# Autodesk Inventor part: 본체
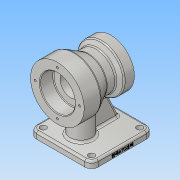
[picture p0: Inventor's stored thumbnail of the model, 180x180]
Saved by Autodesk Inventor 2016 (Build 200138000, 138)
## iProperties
Created: 2019-01
Part Number: 본체
Material: 알루미늄 6061
Document SubType Name: Modeling
Designer: Administrator
Density: 2.7 g/cm^3
Appearance: 알루미늄 - 평지
Mass: 898.816 g
Surface Area: 600.964 cm^2
Volume: 332.895 cm^3
Author: Administrator
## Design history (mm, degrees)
sketch "스케치1"
  geometry: L1 (46, -46)-(-46, -46); L2 (-46, -46)-(-46, 46); L3 (-46, 46)-(46, 46); L4 (46, 46)-(46, -46); L5 (46, -46)-(-46, 46); L6 (-46, -46)-(46, 46); 1 further point
  constraints: 12 end point, 2 midpoint, 2 parallel, 1 horizontal, 1 perpendicular
  dimensions: "d0" = 92 distance of L2.end L3.end; "d1" = 92 distance of L1.end L2.end
extrude "돌출1" new body sketch "스케치1" distance "d2" = 10; taper "d3" = 0 deg
sketch "스케치2"
  geometry: L1 (-51, 80)-(29, 80); L2 (-46, 0)-(-46, 10) reference; L3 (-51, 0)-(-51, 10); L4 (-51, 10)-(-51, 80); L5 (46, 0)-(-46, 0) reference; L6 (-51, 80)-(-51, 120); L7 (-51, 120)-(-26, 120); L8 (-26, 120)-(-5.215, 108); L9 (-5.215, 108)-(8.126, 108); L10 (8.126, 108)-(14, 115); L11 (14, 115)-(29, 115); L12 (29, 115)-(29, 80); 1 further point
  constraints: 20 end point, 3 parallel, 2 perpendicular, 2 vertical, 1 horizontal
  dimensions: "d4" = 80 distance of L1.start L1.end; "d18" = 5 distance between parallel lines of L2 L3; "d19" = 80 distance between parallel lines of L5 L1; "d21" = 30 deg angle of L9 L8; "d22" = 50 deg angle of L9 L10; "d23" = 80 diameter of L7 L1; "d24" = 70 diameter of L11 L1; "d25" = 25 distance of L6.end L7.end; "d26" = 15 distance of L10.end L11.end; "d76" = 80 horizontal distance of L11.end L6.end (derived); "d77" = 56 diameter of L9 L1
revolve "회전1" sketch "스케치2" stored, may be unused: angle "d20" = 90 deg
sketch "스케치3"
  geometry: L1 (-51, 80)-(29, 80); L2 (-51, 80)-(-51, 106); L3 (-51, 106)-(-31, 106); L4 (-31, 106)-(-31, 96); L5 (-31, 96)-(12, 96); L6 (12, 96)-(12, 100); L7 (12, 100)-(29, 100); L8 (29, 100)-(29, 80); L9 (-51, 40)-(-51, 120) reference; 1 further point
  constraints: 16 end point, 5 perpendicular, 2 horizontal, 1 midpoint, 1 vertical
  dimensions: "d28" = 80 distance of L1.start L1.end; "d29" = 52 diameter of L3 L1; "d30" = 20 distance of L2.end L3.end; "d31" = 17 distance of L6.end L7.end; "d32" = 40 diameter of L7 L1; "d33" = 43 distance of L4.end L5.end (derived); "d34" = 32 diameter of L5 L1
revolve "회전2" sketch "스케치3" stored, may be unused: angle "d35" = 90 deg
sketch "스케치4"
  geometry: L1 (0, 0)-(0, 33); L2 (0, 0)-(33, 0); C1 r 16 at (0, 0) reference; A1 r 33 centre (0, 0) between (0, 33) and (33, 0); 5 further points
  constraints: 4 end point, 3 coincident, 2 point on circle, 2 symmetric about line, 1 centre point, 1 horizontal, 1 vertical
  dimensions: "d36" = 66 diameter of A1
hole "구멍1" sketch "스케치4" at (0, 33), (33, 0), (0, -33), (-33, 0) diameter "d37" = 3.242; stored, may be unused: countersink angle "d41" = 90 deg, drill point angle "d43" = 118 deg; dims "d38" = 9, "d39" = 4, "d40" = 2, "d42" = 11
sketch "스케치5"
  geometry: L1 (0, 0)-(0, -27.5); L2 (0, 0)-(-27.5, 0); L3 (0, 0)-(0, 27.5); C1 r 20 at (0, 0) reference; A1 r 27.5 centre (0, 0) between (0, -27.5) and (-27.5, 0); 5 further points
  constraints: 6 end point, 4 coincident, 3 symmetric about line, 2 point on circle, 1 centre point, 1 horizontal, 1 line through centre, 1 vertical, 1 vertical alignment, 2 other
  dimensions: "d44" = 55 diameter of A1
hole "구멍2" sketch "스케치5" at (0, -27.5), (-27.5, 0), (0, 27.5), (27.5, 0) diameter "d45" = 3.242; stored, may be unused: countersink angle "d49" = 90 deg, drill point angle "d51" = 118 deg; dims "d46" = 9, "d47" = 4, "d48" = 2, "d50" = 11
sketch "스케치6"
  geometry: L1 (46, -46)-(-46, -46) reference; L2 (-46, -46)-(-46, 46) reference; C1 r 16 at (0, -16); 1 further point
  constraints: 1 centre point
  dimensions: "d52" = 16 radius of C1; "d53" = 30 distance from line of L1 C1.centre; "d54" = 46 distance from line of C1.centre L2
extrude "돌출2" join sketch "스케치6" stored distance "d55" = 10; taper "d56" = 0 deg
sketch "스케치7"
  geometry: L1 (46, 10)-(-46, 10) reference; L2 (36, 10)-(18.847, 46.785); L3 (46, 0)-(46, 10) reference; 1 further point
  constraints: 2 end point, 1 point on line
  dimensions: "d57" = 10 distance from line of L3 L2.start; "d58" = 25 deg angle of L3 L2
feature "리브1" sketch "스케치7" dims "d59" = 1, "d60" = 10, "d61" = 0, "d62" = 0, "d63" = 1, "d64" = 1
fillet "모깎기1" dims "d65" = 10
sketch "스케치9"
  geometry: C1 r 4.5 at (-36, -36); C2 r 4.5 at (-36, 36); C3 r 4.5 at (36, 36); C4 r 4.5 at (36, -36); A1 r 10 centre (-36, -36) between (-46, -36) and (-36, -46) reference; A2 r 10 centre (-36, 36) between (-36, 46) and (-46, 36) reference; A3 r 10 centre (36, 36) between (46, 36) and (36, 46) reference; A4 r 10 centre (36, -36) between (36, -46) and (46, -36) reference; 1 further point
  constraints: 4 centre point, 4 coincident
  dimensions: "d66" = 9 diameter of C1; "d67" = 9 diameter of C2; "d68" = 9 diameter of C3; "d69" = 9 diameter of C4
extrude "돌출3" cut sketch "스케치9" distance "d70" = 10; taper "d71" = 0 deg
sketch "스케치10"
  geometry: L1 (0, 72)-(0, 0) reference; L2 (-10, -10)-(0, -10) reference; 2 further points
  constraints: 1 other
  dimensions: "d72" = 4 distance from line of L1 point (-4, 36); "d73" = 46 distance from line of point (-4, 36) L2
feature "엠보싱1" sketch "스케치10" dims "d0" = 92, "d1" = 92, "d74" = 0.5, "d75" = 0
fillet "모깎기2" dims "d78" = 3
chamfer "모따기1" distance "d79" = 1; stored, may be unused: second distance "d80" = 2, angle "d81" = 45 deg
fillet "모깎기3" dims "d82" = 1
fillet "모깎기4" dims "d83" = 0.6
fillet "모깎기5" dims "d84" = 3
fillet "모깎기6" dims "d85" = 3
fillet "모깎기7" dims "d86" = 3
feature "분할1"
node "솔리드1"
